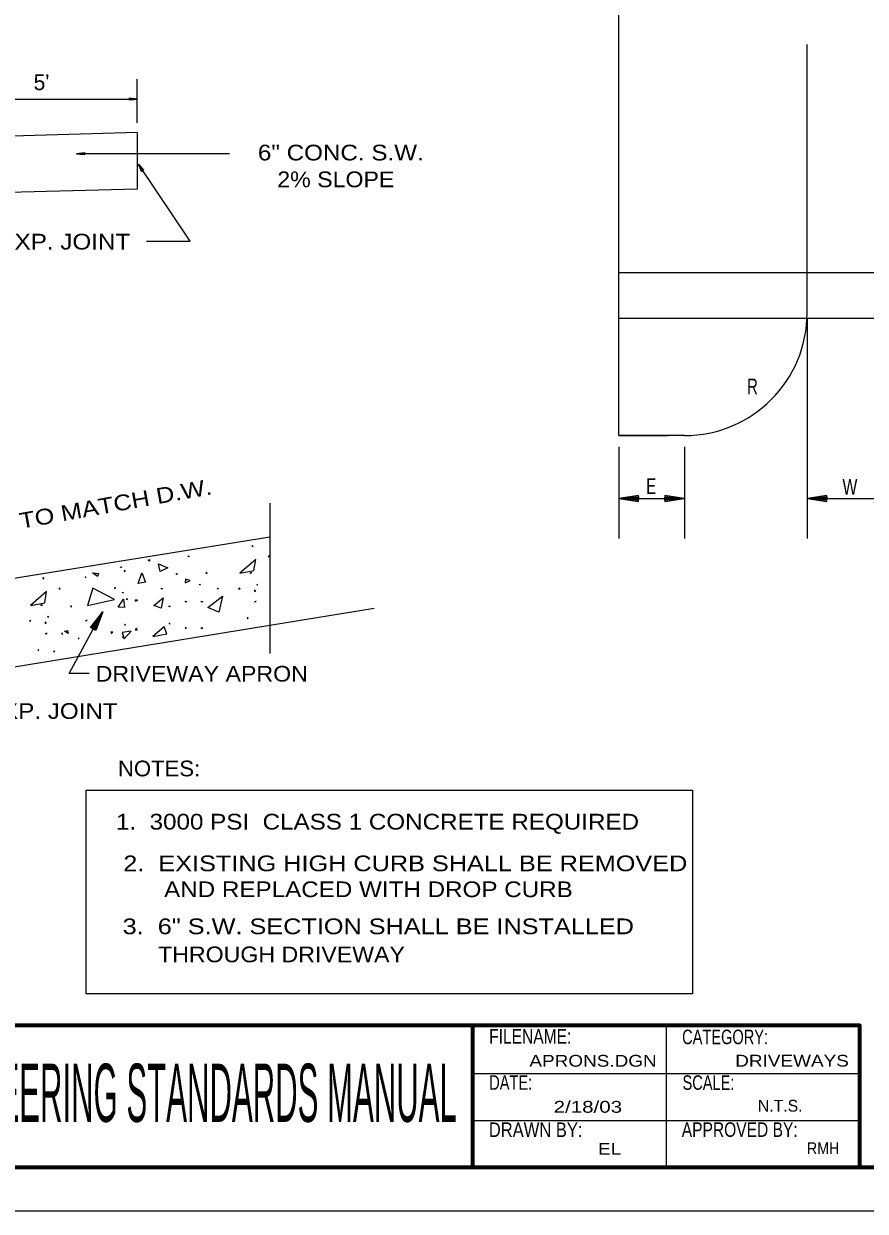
# Model space of a CAD drawing. Extents: x 124.7 to 141.7, y -6.7 to 4.3.
# Drawn here: x 129.63 to 134.08, y -6.71 to -0.42 of the extents above; entities that cross this region are included whole.
import ezdxf
from ezdxf.enums import TextEntityAlignment as Align

# ---------------------------------------------------------------- set-up
doc = ezdxf.new("R2010")
doc.units = 0
doc.header["$LTSCALE"] = 0.033
for name, color, linetype, lineweight in [('1', 7, 'Continuous', 13), ('6', 7, 'Continuous', 13), ('60', 7, 'Continuous', 13), ('8', 7, 'Continuous', 13)]:
    doc.layers.add(name, color=color, linetype=linetype, lineweight=lineweight)
doc.layers.add('62', color=7, linetype='Continuous')

msp = doc.modelspace()

# ---------------------------------------------------------------- linework, layer by layer
at = {"layer": '1'}
for p, q in [((132.77677, -1.97616), (140.44549, -1.97616)), ((133.7739, -1.97616), (133.7739, -3.14385)), ((132.77677, -2.6579), (132.77677, -3.14385)), ((133.12451, -2.6579), (133.12451, -3.14385)), ((132.77677, -2.93135), (133.12451, -2.93135)), ((133.7739, -2.93135), (134.21513, -2.93135))]:
    msp.add_line(p, q, dxfattribs=at)
at = {"layer": '6', "lineweight": 25}
for p, q in [((132.77677, -2.5979), (132.77677, 1.28283)), ((133.77451, -1.9479), (133.77451, -0.52552)), ((130.22682, -0.99256), (130.22682, -1.29244)), ((132.77677, -1.73298), (136.43812, -1.73298)), ((133.12451, -2.5979), (132.77676, -2.5979)), ((132.77677, -2.5979), (133.03932, -2.5979)), ((130.92926, -2.95652), (130.92926, -3.75219)), ((128.09045, -3.59451), (130.92926, -3.13361)), ((128.64341, -3.97384), (131.48223, -3.51295))]:
    msp.add_line(p, q, dxfattribs=at)
at = {"layer": '6'}
for p, q in [((130.22682, -0.94017), (130.22682, -0.70965)), ((129.20005, -0.81446), (130.22682, -0.81446)), ((130.71583, -1.10401), (129.90574, -1.10401))]:
    msp.add_line(p, q, dxfattribs=at)
at = {"layer": '6', "lineweight": 25}
for points in [[(130.22682, -0.99256), (129.20005, -1.02234), (126.96649, -1.29853), (126.85148, -1.33557), (126.56211, -1.24331)], [(130.22682, -1.29244), (129.20005, -1.31806), (126.96649, -1.59245)]]:
    msp.add_lwpolyline(points, dxfattribs=at)
at = {"layer": '6'}
for points in [[(130.27636, -1.56778), (130.5065, -1.56778), (130.23361, -1.16021)], [(129.97154, -3.85832), (129.86568, -3.85832), (130.04302, -3.53275)]]:
    msp.add_lwpolyline(points, dxfattribs=at)
for points in [[(130.83994, -3.18614), (130.83743, -3.182), (130.83294, -3.18381)], [(130.28376, -3.25836), (130.2913, -3.25466), (130.29076, -3.26303)], [(130.49503, -3.2374), (130.49977, -3.23649), (130.50046, -3.24129)], [(130.77017, -3.32783), (130.84499, -3.31332), (130.85429, -3.25478)], [(130.92615, -3.2374), (130.9214, -3.23649), (130.92071, -3.24129)], [(129.98986, -3.32518), (130.02132, -3.32898), (130.01643, -3.34511)], [(130.13853, -3.2972), (130.14041, -3.29274), (130.14474, -3.29487)], [(130.16381, -3.31424), (130.1592, -3.31277), (130.15759, -3.31733)], [(130.23206, -3.3826), (130.2515, -3.32514), (130.2709, -3.37483)], [(130.34857, -3.31892), (130.34009, -3.27756), (130.38895, -3.29873)], [(130.43367, -3.33371), (130.43631, -3.32966), (130.43989, -3.33294)], [(130.5894, -3.32765), (130.59681, -3.32812), (130.59352, -3.32147)], [(130.83177, -3.32765), (130.82434, -3.32812), (130.82765, -3.32147)], [(129.732, -3.35617), (129.72949, -3.35204), (129.725, -3.35384)], [(129.95489, -3.35229), (129.95498, -3.34744), (129.95023, -3.34841)], [(130.48059, -3.37796), (130.50652, -3.36573), (130.48214, -3.35931)], [(130.55716, -3.38964), (130.55817, -3.38489), (130.56181, -3.38808)], [(130.86401, -3.38964), (130.863, -3.38489), (130.85934, -3.38808)], [(129.66223, -3.49785), (129.73705, -3.48335), (129.74635, -3.42481)], [(129.8182, -3.40743), (129.81344, -3.40652), (129.81275, -3.41132)], [(129.9633, -3.49785), (130.10577, -3.46652), (129.99208, -3.40709)], [(130.11333, -3.40508), (130.10852, -3.40467), (130.10634, -3.40898)], [(130.14785, -3.43079), (130.15096, -3.42707), (130.15406, -3.43079)], [(130.31437, -3.49756), (130.36475, -3.45794), (130.35321, -3.51308)], [(130.35134, -3.40827), (130.35618, -3.40801), (130.36067, -3.40982)], [(130.60021, -3.50843), (130.6784, -3.44916), (130.65923, -3.53329)], [(130.64958, -3.4106), (130.65318, -3.40735), (130.65735, -3.40982)], [(130.77159, -3.4106), (130.76799, -3.40735), (130.76382, -3.40982)], [(130.84711, -3.42454), (130.85426, -3.42042), (130.84711, -3.41629)], [(129.72381, -3.49767), (129.71641, -3.49816), (129.7197, -3.4915)], [(129.87954, -3.50373), (129.8769, -3.49969), (129.87333, -3.50297)], [(130.12643, -3.50689), (130.15349, -3.46479), (130.15905, -3.50843)], [(130.17469, -3.46724), (130.17282, -3.46277), (130.16848, -3.4649)], [(130.21637, -3.46905), (130.2266, -3.46781), (130.22256, -3.47729)], [(130.39561, -3.50458), (130.39663, -3.49983), (130.40027, -3.50301)], [(130.48105, -3.4774), (130.4856, -3.47574), (130.48648, -3.4805)], [(130.56415, -3.4774), (130.56892, -3.47653), (130.57348, -3.47817)], [(130.85702, -3.4774), (130.85227, -3.47653), (130.84771, -3.47817)], [(129.66364, -3.58062), (129.66004, -3.5774), (129.65588, -3.57985)], [(129.73917, -3.59457), (129.74629, -3.59045), (129.73917, -3.58632)], [(129.75607, -3.55967), (129.75506, -3.55492), (129.75141, -3.5581)], [(129.96189, -3.5783), (129.95705, -3.57804), (129.95257, -3.57985)], [(130.81431, -3.56434), (130.80955, -3.56348), (130.81044, -3.56824)], [(129.74907, -3.64742), (129.7443, -3.64656), (129.73975, -3.6482)], [(129.83219, -3.64742), (129.82761, -3.64577), (129.82673, -3.65054)], [(129.84154, -3.63512), (129.85704, -3.63068), (129.86147, -3.64619)], [(130.09684, -3.63908), (130.0866, -3.63784), (130.09066, -3.64731)], [(130.15708, -3.67535), (130.1941, -3.63476), (130.14622, -3.64119)], [(130.16536, -3.60082), (130.16226, -3.5971), (130.15917, -3.60082)], [(130.21637, -3.62709), (130.2266, -3.62833), (130.22256, -3.61884)], [(130.30972, -3.66211), (130.38341, -3.64854), (130.36949, -3.61119)], [(130.39561, -3.59156), (130.39663, -3.5963), (130.40027, -3.5931)], [(130.48105, -3.61875), (130.4856, -3.62041), (130.48648, -3.61564)], [(130.56415, -3.61875), (130.56892, -3.6196), (130.57348, -3.61796)], [(129.91761, -3.67461), (129.91659, -3.66986), (129.91295, -3.67305)], [(130.14785, -3.66534), (130.15096, -3.66905), (130.15406, -3.66534)], [(129.70635, -3.73438), (129.70158, -3.73351), (129.70248, -3.73827)], [(129.79024, -3.74136), (129.78609, -3.7389), (129.78557, -3.74371)], [(129.9566, -4.47624), (133.16783, -4.47624), (133.16783, -5.55685), (129.9566, -5.55685)]]:
    msp.add_lwpolyline(points, close=True, dxfattribs=at)
at = {"layer": '6', "lineweight": 25}
msp.add_arc((133.12451, -1.94789), 0.65, 270, 360, dxfattribs=at)
at = {"layer": '60', "lineweight": 70}
msp.add_line((132.00442, -6.47409), (132.00442, -5.7245), dxfattribs=at)
at = {"layer": '60'}
for p, q in [((133.02897, -6.47431), (133.02897, -5.7245)), ((132.00442, -5.97825), (134.05353, -5.97825)), ((132.00442, -6.22815), (134.05353, -6.22815))]:
    msp.add_line(p, q, dxfattribs=at)
msp.add_lwpolyline([(141.66697, -6.70846), (124.65648, -6.70846), (124.65648, 4.29833), (141.66697, 4.29833)], close=True, dxfattribs=at)
at = {"layer": '60', "lineweight": 70}
msp.add_lwpolyline([(140.98583, 4.08146), (124.91782, 4.08146), (124.91782, -6.47409), (140.98583, -6.47409)], close=True, dxfattribs=at)
msp.add_lwpolyline([(134.05352, -6.47397), (134.05352, -5.72428), (128.93787, -5.72428)], dxfattribs=at)
at = {"layer": '8'}
for points in [[(130.22714, -0.81467), (130.18565, -0.82062), (130.18565, -0.80773), (130.22728, -0.81452)], [(130.18568, -0.81856), (130.22734, -0.8144), (130.18568, -0.8144), (130.18568, -0.81231), (130.22734, -0.8144), (130.18568, -0.81023), (130.18568, -0.81648), (130.22526, -0.8144)], [(129.94689, -1.09991), (129.90522, -1.10407), (129.94689, -1.10407), (129.94689, -1.10616), (129.90522, -1.10407), (129.94689, -1.10824), (129.94689, -1.10199), (129.9073, -1.10407)], [(129.90543, -1.1038), (129.94692, -1.09784), (129.94692, -1.11074), (129.90528, -1.10395)], [(130.2585, -1.19324), (130.23329, -1.1598), (130.25494, -1.19541), (130.25316, -1.19649), (130.23329, -1.1598), (130.25137, -1.19757), (130.25672, -1.19432), (130.23438, -1.16158)], [(130.23364, -1.15983), (130.26027, -1.1922), (130.24925, -1.1989), (130.23344, -1.15979)], [(132.88094, -2.94177), (132.77677, -2.93135), (132.88094, -2.93135), (132.88094, -2.92615), (132.77677, -2.93135), (132.88094, -2.92094), (132.88094, -2.93656), (132.78198, -2.93135)], [(132.77729, -2.93203), (132.88102, -2.94693), (132.88102, -2.91469), (132.77693, -2.93167)], [(133.12399, -2.93068), (133.02026, -2.91578), (133.02026, -2.94802), (133.12435, -2.93104)], [(133.02034, -2.92094), (133.12451, -2.93135), (133.02034, -2.93135), (133.02034, -2.93656), (133.12451, -2.93135), (133.02034, -2.94177), (133.02034, -2.92615), (133.1193, -2.93135)], [(133.87806, -2.94177), (133.7739, -2.93135), (133.87806, -2.93135), (133.87806, -2.92615), (133.7739, -2.93135), (133.87806, -2.92094), (133.87806, -2.93656), (133.7791, -2.93135)], [(133.77442, -2.93203), (133.87814, -2.94693), (133.87814, -2.91469), (133.77405, -2.93167)], [(130.04385, -3.53231), (130.00732, -3.63053), (129.97901, -3.6151), (130.04371, -3.53182)], [(130.00283, -3.62799), (130.04351, -3.53153), (129.99368, -3.62301), (129.9891, -3.62052), (130.04351, -3.53153), (129.98453, -3.61803), (129.99826, -3.6255), (130.04102, -3.5361)]]:
    msp.add_lwpolyline(points, dxfattribs=at)

# ---------------------------------------------------------------- texts
at = {"layer": '6'}
msp.add_text("5'", height=0.08333, dxfattribs=at).set_placement((129.67801, -0.7673))
for s, width, p in [('6" CONC. S.W.', 1.15, (130.86571, -1.13983)), ('2% SLOPE', 1.1, (130.96843, -1.28179)), ('1/2" EXP. JOINT', 1.15, (129.23241, -1.61189)), ('R', 0.7, (133.45686, -2.37917)), ('E', 0.7, (132.92258, -2.90775)), ('W', 0.75, (133.96165, -2.91046)), ('DRIVEWAY APRON', 1.1, (130.00652, -3.90171)), ('1/2" EXP. JOINT', 1.15, (129.16601, -4.09927)), ('NOTES:', 1.05, (130.1246, -4.40366)), (' 1.  3000 PSI  CLASS 1 CONCRETE REQUIRED', 1.15, (130.07848, -4.68568)), ('2.  EXISTING HIGH CURB SHALL BE REMOVED ', 1.2, (130.15287, -4.9066)), ('AND REPLACED WITH DROP CURB', 1.15, (130.36894, -5.04398)), ('3.  6" S.W. SECTION SHALL BE INSTALLED', 1.2, (130.14956, -5.24025)), ('THROUGH DRIVEWAY', 1.1, (130.337, -5.38903))]:
    msp.add_text(s, height=0.08333, dxfattribs=dict(at, width=width)).set_placement(p)
at = {"layer": '6', "width": 1.2}
msp.add_text('SLOPE TO MATCH D.W.', height=0.08333, rotation=10.26, dxfattribs=at).set_placement((129.13573, -3.1782))
at = {"layer": '60'}
for s, width, p in [('FILENAME:', 0.8, (132.09061, -5.82027)), ('CATEGORY:', 0.75, (133.11257, -5.82315)), ('DATE:', 0.75, (132.09081, -6.06474)), ('SCALE:', 0.75, (133.11462, -6.06511)), ('DRAWN BY:', 0.85, (132.08871, -6.315)), ('APPROVED BY:', 0.8, (133.11058, -6.3143))]:
    msp.add_text(s, height=0.07704, dxfattribs=dict(at, width=width)).set_placement(p)
at = {"layer": '60', "width": 0.4}
msp.add_text('ENGINEERING STANDARDS MANUAL', height=0.3082, dxfattribs=at).set_placement((130.44425, -6.2348), align=Align.CENTER)
at = {"layer": '62', "width": 1.2}
for s, p in [('APRONS.DGN   ', (133.06135, -5.94239)), ('  DRIVEWAYS', (133.99549, -5.94189))]:
    msp.add_text(s, height=0.0625, dxfattribs=at).set_placement(p, align=Align.RIGHT)
at = {"layer": '62'}
for s, width, p in [('2/18/03 ', 1.3, (132.43202, -6.18636)), ('EL ', 1.2, (132.66692, -6.40865)), ('RMH', 0.9, (133.77359, -6.4055))]:
    msp.add_text(s, height=0.0625, dxfattribs=dict(at, width=width)).set_placement(p)
msp.add_text('N.T.S.', height=0.0625, dxfattribs=at).set_placement((133.51344, -6.18059))

doc.saveas('drawing.dxf')
